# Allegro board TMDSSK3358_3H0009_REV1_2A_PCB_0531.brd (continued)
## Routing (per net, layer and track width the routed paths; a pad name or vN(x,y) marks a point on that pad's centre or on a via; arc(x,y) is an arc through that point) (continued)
GND_IN: length 38
  TOP w0.889: J9.2 110.25,11.48 ; J9.2 108.1,13.63 ; J9.2 105.96,11.48 ; J9.2 108.1,9.33 ; J9.3 114.74,10.07 ; J9.3 114.74,6.39 ; J9.3 111.06,10.07 ; J9.3 111.06,6.39
  BOTTOM w0.889: 111.06,6.39 J9.3 ; J9.3 114.74,10.07 ; J9.3 114.74,6.39 ; J9.3 111.06,10.07 ; J9.2 110.25,11.48 ; J9.2 105.96,11.48 ; J9.2 108.1,9.33 ; J9.2 108.1,13.63
GND_OSC0: length 22.4
  TOP w0.508: v2(64.19,34.09) 64.87,33.4 C95.2
  BOTTOM w0.305: v2(64.19,34.09) 64.45,33.82 65.2,33.82 65.59,34.21 U26.V11
  BOTTOM w0.381: C250.1 60.41,26.44 57.33,26.44 55.82,27.95 55.82,29.19 56.37,29.75 56.37,30.51 57,31.14 60.36,31.14 C245.1 62.22,32.44 62.22,32.75 63.28,33.82 63.92,33.82 v2(64.19,34.09)
GND_OSC1: length 10.3
  BOTTOM w0.381: C249.1 C247.1 89.02,28.82 88.73,28.82 88.27,29.28 87.37,29.28 87.08,28.99 82.52,28.99 82.09,29.41 U26.A5
GNDA_ADC: length 23.3
  TOP w0.381: 84.26,28.79 FB8.1 84.3,28.73 85.39,27.64 88.19,27.64 89.03,26.8 92.68,26.8 93.73,27.84 93.73,30.34 92.95,31.11 92.95,32.98 92.53,33.4 90.04,33.4 89.66,33.02 88,33.02 87.93,33.09 87.46,33.09 87.45,33.08 87.31,33.08 R72.1
  BOTTOM w0.305: v2(77.54,31.41) 77.14,31.81 U26.E8
GNDA_TSC: length 12.8
  TOP w0.508: R72.2 85.9,32.84 83.51,32.84 v2(83.11,33.24) 82.93,33.43 82.93,34.92 82.58,35.28 81.51,35.28 C89.2 C88.2
  LYR4_PWR1 w0.381: v2(83.11,33.24) 81.95,33.24 80.92,32.21 v2(79.14,32.21)
  BOTTOM w0.381: v2(83.11,33.24) 83.11,33.13 82.59,32.61
V1_8D: length 16
  TOP w0.381: C170.1 52.59,6.36 U12.16 ; U11.16 49.16,13.35 49.17,13.34 C149.1 49.07,12.75 v1(48.77,12.45)
  TOP w0.508: R58.2 16.97,37.41 v1(16.97,38.18) ; v1(50.72,7.92) 50.72,7.42 51.79,6.35 C170.1 ; R57.2 15.45,37.67 v1(15.45,37.92)
  BOTTOM w0.254: C276.1 35.97,14.96 U31.36
  BOTTOM w0.381: U29.16 51.67,20.7 51.29,21.08 C264.1
  BOTTOM w0.508: v1(49.66,21.46) 50.09,21.46 50.42,21.13 C264.1 ; C276.1 v1(35.31,16.34)
  BOTTOM w0.635: C270.1 v1(34.36,17.67)
  vias: v1(16.21,38.18) v1(17.86,38.18) v1(18.62,38.18) v1(29.17,15.19) v1(29.17,14.43) v1(30.05,15.19) v1(30.05,14.43)
V3_3AUD:
  vias: v1(35.2,8.33) v1(35.9,7.82) v1(40.42,6.73) v1(40.79,7.8)
V3_3D: length 115.7
  TOP w0.254: J1.4 32.81,34.66 v1(32.59,34.87) ; v1(97.48,18.14) 97.48,18.57 97.33,18.72 97.01,18.72 96.88,18.59 U10.1 ; 45.61,4.71 FB11.1
  TOP w0.305: U10.15 v1(96.39,17.02) ; U12.3 v1(58.7,7.66) ; U10.14 v1(98.21,16.52)
  TOP w0.381: U12.1 59.26,6.36 58.81,5.91 58.81,5.43 C180.1 ; U5.5 v1(40.71,51.83) ; C38.1 94.36,43.85 v1(94.87,44.36) 95.5,43.72 C39.1 ; U11.1 58.41,13.35 C151.1 v1(58.55,12.51) ; U11.2 58.32,14 v1(58.46,14.14)
  TOP w0.508: C15.1 42.29,53.59 42.32,53.56 v1(42.32,53.51) ; v1(44.34,4.71) 45.61,4.71 44.79,3.89 v1(44.79,3.51) ; R13.2 37.78,54.48 v1(37.5,54.76) ; C35.1 55.12,43.64 54.48,44.28 54.48,44.28 v1(54.46,44.3) 54.44,44.3 53.97,43.83 C34.1 ; v1(47.81,24.13) 47.45,24.49 R76.1 ; R82.1 v1(39.58,21.08) ; J2.1 62.51,23.4 62.1,22.99 61.72,22.99 v1(61.47,22.73) ; FB11.1 v1(46.95,4.71) ; C5.1 44.89,60.58 44.83,60.52 v1(44.83,60.2) ; v1(50.43,57.24) C12.1 ; R16.1 v1(51.31,51.56) ; C180.1 v1(59.11,4.41) ; v1(40.52,57.91) 40.95,57.91 41.08,57.78 C11.1 ; v1(89.05,11.61) 88.61,11.16 R90.1 ; C133.1 v1(41.33,25.98) ; v1(42.33,21.08) R83.1 ; C16.1 44.32,53.56 44.32,53.56 v1(44.32,53.51) ; v1(39.75,18.29) 40.45,18.29 40.91,17.83 C139.1 ; U4.5 v1(49.78,51.95) ; C14.1 47.53,56.64 47.43,56.74 v1(47.05,56.74) 46.56,56.74 46.54,56.77 C13.1 ; R86.2 v1(92.58,15.42) ; C184.2 101.17,2.85 v1(101.17,1.95) ; U9.6 v1(46.93,23.29)
  LYR4_PWR1 w0.635: J8.4 34.15,47.24 ; J8.4 32.14,47.24 ; J8.4 33.15,46.24 ; J8.4 33.15,48.25 ; J11.1 102.35,13.21 ; J11.1 100.34,13.21 ; J11.1 101.35,14.21
  LY6_SIG2 w0.381: v1(55.75,21.67) 56.47,21.67 57.22,22.42 61.07,22.42 61.39,22.73 v1(61.47,22.73)
  BOTTOM w0.203: 54.63,43.53 U24.4 ; U23.4 95.01,43.69
  BOTTOM w0.254: U28.42 33.54,29.58 C246.1 ; U31.45 41.08,16.26 v1(41.33,16.51) 41.58,16.26 U31.46 ; U31.44 40.58,16.64 40.64,16.69 C272.1 ; v1(94.87,44.36) 95.01,44.21 95.01,43.69 ; 54.63,43.53 54.63,44.14 v1(54.46,44.3)
  BOTTOM w0.305: U16.20 40.64,57.79 v1(40.52,57.91) ; U28.20 42.92,21.72 43.05,21.58 C265.1 ; U28.28 v1(38.92,24.51) ; U16.27 44.82,60.19 v1(44.83,60.2) ; C272.1 40.26,17.27 40.13,17.4 v1(39.75,17.4) ; U29.3 v1(52.97,23.8) ; U28.31 37.42,21.97 37.59,21.8 C266.1 ; v1(39.94,32.55) 39.98,32.55 40.42,33 U28.56 ; v1(47.05,56.74) 47.14,56.74 47.09,56.79 U16.4 ; U16.14 v1(42.32,53.51) ; U16.10 v1(44.32,53.51) ; U29.2 52.32,24.07 v1(52,23.75) 51.67,24.07 U29.1
  BOTTOM w0.381: v1(98.21,16.52) 97.1,16.52 C275.1 ; C246.1 32.9,29.59 v1(32.47,29.16) ; C265.1 v1(42.33,21.08) ; R110.2 v1(49.74,53.29) ; C194.2 49.54,52.2 v1(49.78,51.95) ; R225.2 62.95,21.33 62.95,21.96 62.18,22.73 v1(61.47,22.73) ; C266.1 v1(36.83,21.08)
  BOTTOM w0.508: FB16.1 v1(104.3,46.15) ; v1(40.85,37.41) 40.15,37.41 FB18.1 ; C259.1 49.23,22.99 v1(48.73,23.48) ; v1(37.5,54.76) 37.78,54.48 R13.2 ; v1(101.17,1.95) J12.5 ; v1(62.45,48.31) 62.45,48.18 62.86,47.76 FB15.1 v1(63.99,47.23) ; C196.2 43.96,52.32 44.21,52.58 v1(44.63,52.58) ; R118.2 v1(42.6,50.55) ; 95.77,16.2 95.77,16.4 v1(96.39,17.02) ; v1(32.59,34.87) 32.65,34.93 32.65,34.93 33.02,35.3 33.1,35.38 C231.1 ; R221.2 v1(47.81,24.13) ; v1(89.05,11.61) 89.15,11.61 89.93,12.39 89.93,13.66 90.86,14.59 90.86,15.2 90.69,15.36 90.69,16.71 91.2,17.22 R234.2 v1(91.52,18.03)
  vias: v1(53.85,29.01) v1(54.29,28.04) v1(114.17,49.28) v1(114.43,48.64) v1(114.55,49.91)
V5_0D: length 24.3
  TOP w0.508: R15.2 32.52,52.2 26.63,46.3 20.15,46.3 19.52,46.93 18.88,46.93
  BOTTOM w0.203: 22.4,47.03 U20.E1 U20.E2 22,46.99
  vias: v1(16.34,47.57) v1(17.23,47.57) v1(18.12,47.57) v1(18.88,47.57)
V5_0D_EN: length 1.7
  BOTTOM w0.14: U20.A4 20.86,49.86 20.15,49.86 R120.1
VBAT: length 38.1
  TOP w0.254: 25.87,40.45 U7.2
  TOP w0.508: C43.1 112.12,43.24 112.24,43.36 v1(112.29,43.36) ; C46.1 116.96,42.33 117.06,42.43 117.75,42.43 v1(117.89,42.57) ; C63.1 110.17,38.77 110.04,38.64 v1(110.04,38.58) ; v1(113.97,43.51) 113.92,43.46 113.92,43.4 113.7,43.18 C42.1
  TOP w0.635: TP11.1 113.08,25.4 ; TP11.1 112.01,26.47 ; TP11.1 110.95,25.4 ; TP11.1 112.01,24.33
  LY5_PWR2 w0.635: TP5.1 119.18,48.51 ; TP5.1 118.11,49.58 ; TP5.1 117.04,48.51 ; TP11.1 112.01,26.47 ; TP11.1 112.01,24.33 ; TP11.1 113.08,25.4
  BOTTOM w0.14: 117.02,41.58 U25.13
  BOTTOM w0.203: v1(112.29,43.36) 112.65,43.01 U25.3 ; 115.25,35.43 115.25,35.08 115.37,34.95 v1(115.72,34.95) ; 115.25,35.43 115.05,35.63 U25.28 ; 115.25,35.43 115.45,35.63 U25.27 ; v1(110.04,38.58) 110.1,38.64 U25.41 ; U25.6 113.85,43.39 v1(113.97,43.51) ; U25.36 111.85,35.87 111.62,35.65 ; U25.47 110.11,41.04 109.85,41.3 ; U25.23 117.83,37.44
  BOTTOM w0.254: U20.A2 U20.A1
  BOTTOM w0.381: 117.02,41.58 117.02,41.7 v1(117.89,42.57) ; v1(111.3,34.95) 111.3,35.33 111.62,35.65 ; 109.85,41.3 109.65,41.5 v1(109.02,41.5) ; 117.83,37.44 118.16,37.44 v1(118.41,37.19)
  BOTTOM w0.508: R112.2 v1(130.18,51.18) ; R113.2 v1(129.03,51.18) ; R111.2 v1(132.21,51.94) ; R114.2 127.89,51.44 v1(128.14,51.18) ; R116.2 v1(125.6,51.18)
  BOTTOM w0.635: TP11.1 113.08,25.4 ; TP11.1 112.01,26.47 ; TP11.1 112.01,24.33 ; TP11.1 110.95,25.4
  vias: v1(22.43,50.5) v1(23.42,50.53) v1(25.23,43.76) v1(25.61,41.73) v1(25.61,41.1) v1(25.86,43.76) v1(30.05,24.71) v1(30.05,23.95) v1(30.82,24.71) v1(30.82,23.95) v1(31.96,14.55) v1(31.96,13.67) v1(32.72,14.55) v1(32.72,13.67) v1(61.84,3.62) v1(62.29,2.67) v1(86.36,4.83) v1(87.12,4.83) v1(87.25,1.78) v1(108.54,50.18) v1(109.09,49.53) v1(109.18,50.18) v1(109.6,24.26) v1(109.6,22.99) v1(109.6,20.19) v1(110.74,24.26) v1(110.74,22.99) v1(110.74,20.19) v1(112.14,23.88) v1(112.14,22.61) v1(112.14,21.34) v1(112.14,20.19) v1(113.28,23.88) v1(113.28,22.61) v1(113.28,21.34) v1(113.28,20.19) v1(113.54,25.15) v1(114.43,20.19) v1(115.7,20.19) v1(117.02,24.13) v1(117.02,22.86) v1(117.02,21.59) v1(117.09,25.53) v1(117.74,33.47) v1(120.27,45.97) v1(120.27,45.21) v1(120.27,44.32) v1(120.27,43.56) v1(120.9,45.98) v1(121.03,45.21) v1(121.03,44.32) v1(121.03,43.56) v1(121.92,44.83)
VBAT_WLAN:
  vias: v1(19.64,39.7) v1(19.73,38.86) v1(20.28,38.3)
VBAT_WLAN_OUT: length 1
  BOTTOM w0.381: U22.2 19.74,44.81 20.31,44.24
VBUS_DET: length 3.5
  BOTTOM w0.254: R103.1 39.6,56.46 40.11,56.46 40.44,56.79 U16.18
  BOTTOM w0.381: R101.2 R103.1
VDD_1V8FT: length 13.3
  BOTTOM w0.305: U28.49 36.92,32.65 v1(36.96,32.6) ; 47.73,27.08 U28.12 ; v1(44.91,31.27) 44.42,31.76 U28.64 ; C251.2 33.66,27.08 U28.37
  BOTTOM w0.508: v1(50.5,26.04) C253.2 49.2,26.04 48.16,27.08 47.73,27.08 ; v1(32.7,32.26) 33.2,32.77 C241.2 ; v1(32.72,27) C251.2
VDD_CORE: length 22.6
  TOP w0.254: v2(72.74,29.81) 72.74,30.14 72.75,30.15 ; v1(90.8,38.98) 90.3,39.48 90.3,39.5 89.77,40.02 C49.1 88.15,40.02 C51.1 87.96,40 87.66,40.3 87.66,40.45 87.64,40.5 87.63,40.51 87.63,40.51 v1(87.63,40.51)
  TOP w0.381: C100.1 70.93,32 v2(71.14,32.21) ; v2(73.54,35.41) 73.59,35.36 C92.1 ; 72.73,31.4 72.73,31.4 v2(72.74,31.41) 73.33,32 C102.1 ; C101.1 72.15,32.21 v2(72.74,32.21) ; C91.1 71.25,34.72 v2(71.14,34.61)
  BOTTOM w0.14: 71.14,36.21 v2(71.14,36.21)
  BOTTOM w0.203: 110.24,39.84 U25.44
  BOTTOM w0.305: U26.L7 72.34,31.01 v2(72.74,31.41) U26.K8 ; U26.L8 72.34,31.82 v2(72.74,32.21) 72.34,32.61 U26.L9 ; v2(75.94,29.81) 75.94,29.81 ; 75.94,29.81 U26.F6 ; 75.94,29.81 75.54,30.21 U26.G6 ; U26.N8 70.74,31.82 v2(71.14,32.21) 70.74,32.61 U26.N9 ; v2(75.14,34.61) U26.H11 ; U26.K6 v2(72.74,29.81) 72.74,29.81 U26.L6 ; U26.G10 v2(75.14,33.01) ; U26.M13 71.14,36.21 U26.N13 ; U26.F7 v2(75.94,30.61) 75.54,31.01 U26.G7 ; U26.N12 v2(71.14,34.61) U26.M11 ; U26.J12 v2(73.54,35.41) 73.14,35.02 U26.K12
  BOTTOM w0.381: 110.24,39.84 109.9,39.84 109.87,39.81 108.98,39.81 108.58,39.42
  vias: v1(103.33,39.14) v1(103.38,40.67) v1(103.35,39.9) v1(104.19,40.64) v1(104.96,41.96) v1(104.98,41.3) v1(104.98,40.64) v1(105.92,40.64) v1(105.98,41.91)
VDD_FTVPHY: length 4.8
  BOTTOM w0.305: U28.4 47.65,31.08
  BOTTOM w0.508: FB19.2 50.36,30.99 C242.1 48.11,30.99 48.02,31.08 47.65,31.08
VDD_FTVPLL: length 5
  BOTTOM w0.305: U28.9 47.35,28.58 47.54,28.77
  BOTTOM w0.508: FB20.2 50.65,28.66 49.19,28.66 C248.1 48.82,29.03 47.8,29.03 47.54,28.77
VDD_MPU_AM335X: length 7
  TOP w0.305: C82.1 76.55,36.83 76.23,36.51 76.23,36.51 v2(75.94,36.21) ; C86.1 77.47,34.54 v2(76.74,33.81) ; v2(74.34,36.21) 74.45,36.32 C85.1
  BOTTOM w0.14: v2(75.94,36.21) 75.94,36.21
  BOTTOM w0.305: v2(75.94,34.61) U26.F12 ; U26.G13 75.94,36.21 U26.F13 ; U26.J13 73.94,35.82 v2(74.34,36.21) U26.H13 ; U26.F11 v2(76.74,33.81) 76.34,33.41 U26.F10
  vias: v1(89.8,30.72) v1(90.19,30.22) v1(90.3,29.6) v1(101.11,29.54) v1(101.11,28.77) v1(101.87,28.52) v1(103.12,29.46) v1(103.12,28.57) v1(103.67,33.24) v1(103.73,31.44) v1(104.39,29.46) v1(104.39,28.57) v1(104.71,32.39) v1(104.71,31.5) v1(104.82,33.18) v1(106.23,33.12)
VDD_RTC: length 2.4
  TOP w0.381: C122.1 79.68,29.29 78.87,29.29 v2(78.34,29.81)
  BOTTOM w0.305: U26.D6 v2(78.34,29.81)
VDDA_ADC: length 2.5
  TOP w0.381: C99.1 79.8,32.13 79.34,31.67 78.6,31.67 v2(78.34,31.41)
  BOTTOM w0.305: v2(78.34,31.41) 78.34,31.42 U26.D8
VDDH_PHY: length 15.1
  TOP w0.508: C41.1 97.72,43.69 v1(97.59,43.81) 97.59,44.91 97.03,45.47 R26.1 94.77,45.47 93.6,44.29 93.6,38.71 94.72,37.59 R55.1
  BOTTOM w0.203: U23.10 97.41,43.63 v1(97.59,43.81)
VDDH_PHY2: length 14.7
  TOP w0.381: R54.1 54.22,37.92 54.22,38.72 54.55,39.05 54.66,39.05 55.05,39.43 55.05,39.96 54.61,40.4 54.17,40.4 52.89,41.68 R47.2
  TOP w0.508: v1(52.89,44.25) R47.2 ; C37.1 57.4,43.31 v1(57.03,43.69)
  LY3_SIG1 w0.508: v1(57.03,43.69) 56.77,43.94 55.63,43.94 55.19,43.51 53.63,43.51 v1(52.89,44.25)
  BOTTOM w0.203: v1(57.03,43.69) U24.10
VDDL_PHY: length 2.2
  BOTTOM w0.203: U23.47 90.7,41.55
VDDL_PHY2: length 1.8
  BOTTOM w0.203: C223.1 50.82,41.55 U24.47
VDDMPU_MON: length 7.7
  BOTTOM w0.381: U26.A2 80.85,26.5 81.27,26.5 82.38,25.4 82.83,25.4 85.62,22.61 R223.1
VDDS_DDR: length 46.2
  TOP w0.254: v2(79.51,7.2) 79.56,7.15 C174.1 ; C168.1 70.35,7.57 v1(69.77,6.99) ; v1(64.27,15.37) 64.26,15.37 64.26,15.39 64.29,15.37 64.29,15.02 64.34,14.96 C144.1 ; C142.1 77.71,16.57 v2(77.5,16.78) ; C143.1 72.07,16.13 v1(71.43,16.76) ; C175.1 70.78,6.84 v1(70.65,6.97) ; C169.1 69.25,7.35 v1(68.89,7) ; v2(69.91,13.6) 70.01,13.69 C148.1 ; v2(73.91,7.19) 73.81,7.09 C173.1 ; U14.2 87.19,3.8 87.01,3.98 ; C172.1 77.46,6.85 v2(77.11,7.2) ; v2(72.31,10.4) 72.32,10.39 C165.1 ; v2(75.51,13.6) 75.77,13.85 C147.1
  TOP w0.305: C167.2 74.74,8.8 v2(75.51,8.8)
  TOP w0.381: 87.01,3.98 86.82,4.17 86.21,4.17 85.83,4.55 85.79,4.59 85.79,5.06 86.11,5.38 v1(86.11,8.15)
  TOP w0.508: v1(62.41,10.79) 62.65,10.56 C158.1 ; R93.2 86.97,9.02 v1(86.11,8.15) ; v1(87.1,15.72) 87.1,16.48 C140.1
  BOTTOM w0.203: 117.68,40.24 U25.16
  BOTTOM w0.254: v2(79.13,14.55) 79.13,14.57 79.09,14.52 79.11,14.5 U32.R1 ; 118.27,40.39 117.83,40.39 117.68,40.24
  BOTTOM w0.305: U32.G7 72.71,9.99 v2(72.31,10.4)
  BOTTOM w0.381: U32.H9 v2(73.91,7.19) ; U32.D2 v2(69.91,13.6) ; v1(71.43,16.76) 71.43,15.04 71.75,14.73 71.75,14.16 U32.F1 ; U32.N1 77.51,16.73 77.56,16.78 v2(77.5,16.78) ; U32.D9 69.77,7.05 v1(69.77,6.99) ; U32.R9 v2(79.51,7.2) ; U32.N9 v2(77.11,7.2) ; v1(64.32,8.89) 64.81,8.39 U32.A8 ; U32.C9 68.89,6.97 v1(68.89,7) ; U32.K8 v2(75.51,8.8) ; v1(68.77,15.59) 69.51,14.85 U32.C1 ; v1(70.65,6.97) 70.65,7.13 U32.E9 ; U32.K2 v2(75.51,13.6) ; U32.A1 v2(68.31,13.6) U32.B2 ; U32.H2 v2(73.11,13.6)
  BOTTOM w0.508: v1(87.1,15.72) 86.82,15.44 R237.1 ; C140.1 86.69,17.77 v1(86.95,18.03)
  vias: v1(59.81,11.91) v1(60.82,12.21) v1(61.31,14.61) v1(61.31,13.97) v1(61.33,13.34) v1(120.14,34.29) v1(120.9,35.05) v1(120.9,34.29) v1(121.79,35.05) v1(121.79,34.29) v1(122.68,36.58) v1(122.68,35.81) v1(122.68,35.05) v1(122.68,34.29) v1(123.44,35.81) v1(123.44,35.05) v1(123.44,34.29)
VDDS_DDR3_AM335X: length 4
  BOTTOM w0.305: v2(75.94,29.01) U26.G5 ; U26.L5 72.74,29.01 v2(72.74,29.01) U26.K5 ; U26.H5 v2(74.34,29.01) 74.34,29.01 U26.J5 ; U26.E5 v2(76.74,29.01) 76.74,29.01 U26.F5
  vias: v1(59.33,17.49) v1(59.63,18.64) v1(60.01,18.13) v1(60.44,18.6) v1(61.72,20.7)
VDDSHV1: length 73.1
  TOP w0.508: 64.77,49.53 66.92,49.53 68.17,50.77 71.08,50.77 71.44,50.41 74.05,50.41 76.24,52.6 89.4,52.6 89.62,52.38 91.19,52.38 93.01,50.56 96.44,50.56 v1(96.79,50.21) 96.79,49.42 v1(96.86,49.35)
  LY6_SIG2 w0.508: v1(96.79,50.21) 96.79,49.42 v1(96.86,49.35) 96.98,49.23 103.83,49.23 109.85,55.25 109.85,55.25 110.01,55.4 112.81,55.4 113.68,54.53 120.21,54.53 120.26,54.48 123.2,54.48 126.24,51.44 v1(126.24,51.18)
  BOTTOM w0.254: U26.P8 v2(69.54,31.41) U26.P7
  BOTTOM w0.508: v1(126.24,51.18) 126.75,51.69 R115.1 ; v1(96.86,49.35) 96.45,48.95 R123.1
VDDSHV2: length 2
  TOP w0.305: v2(69.54,33.81) 69.78,33.57 C96.1
  BOTTOM w0.305: U26.P10 v2(69.54,33.81) ; U26.P11 69.94,34.22 v2(69.54,34.61)
  vias: v1(64.53,43.76) v1(64.78,43.12)
VDDSHV3: length 119.6
  TOP w0.508: SW3.1 SW3.2 127.15,34.14 v1(127,34.29) ; R22.2 51.37,49.45 51.76,49.85 52.53,49.85 52.54,49.85 v1(52.57,49.85)
  LY3_SIG1 w0.381: v1(52.57,49.85) 52.06,50.37 52.06,51.94 52.72,52.6 55.76,52.6 56.15,52.99 57.53,52.99 58.16,52.35 67.43,52.35 69.21,50.57 69.21,49.13 v1(70.33,48) 70.33,47.45 v1(70.41,47.37)
  LY3_SIG1 w0.508: v1(127,34.29) 127,48.02 121.6,53.42 120.28,53.42 116.18,57.52 110.6,57.52 108.4,55.32 101.79,55.32 99.07,58.04 98.54,58.04 97.64,57.14 95.59,57.14 93.55,55.1 91.36,55.1 90.47,56 78.78,56 77.3,54.52 v1(75.95,54.52) v1(74.81,54.52)
  LY6_SIG2 w0.508: v1(75.95,54.52) 75.61,54.86 75.15,54.86 v1(74.81,54.52) 74.81,53.49 73.73,52.41 73.73,50.86 73.35,50.49 72.81,50.49 v1(70.33,48) 70.33,47.45 v1(70.41,47.37)
  BOTTOM w0.305: v2(69.54,35.41) U26.P12 ; U26.P13 v2(69.54,36.21)
VDDSHV4: length 43.9
  TOP w0.254: v1(103.13,65.96) 103.44,65.66 U1.10
  TOP w0.305: v2(74.34,37.01) 74.04,37.01 73.97,37.08 C80.1
  TOP w0.508: v1(99.35,63.75) C3.1 99.18,62.56 96.95,62.56 v1(96.93,62.59) ; R1.2 v1(101.15,68.76) ; v1(96.58,68.33) C1.1 ; R4.2 v1(101.98,65.84) ; R5.2 v1(99.3,64.82) ; R2.2 v1(108.08,67.18) ; R3.2 v1(101.91,66.93)
  BOTTOM w0.305: U26.J14 v2(74.34,37.01) U26.H14 v2(75.14,37.01) ; v1(96.58,68.33) 97.54,68.33 J4.4
  BOTTOM w0.508: v1(96.93,62.59) 96.9,62.56 v1(96.27,62.56) 94.36,60.66 94.36,56.13 93.09,54.86 91.95,54.86 90.69,56.12 80.19,56.12 77.56,53.49 77.56,50.18 v1(77.56,50.18) 77.56,50.07 78.05,49.58 v1(78.05,49.58)
VDDSHV5: length 2
  TOP w0.305: C79.1 72.32,37.08 72.39,37.01 v2(72.74,37.01)
  BOTTOM w0.254: U26.L14 72.34,36.62 v2(72.74,37.01) U26.K14
VDDSHV6: length 70.9
  TOP w0.254: 98.81,59.3 U2.1
  TOP w0.381: C116.1 70.28,29.01 v2(69.54,29.01) v2(69.54,29.81) ; v1(103.36,30.84) 103.73,30.46 R74.2 ; v1(85.72,44.3) 85.72,44.31 86.93,44.31 87.26,44.64 U6.5 ; U8.8 102.23,28 102.46,28.23 C115.1 102.19,29.08 101.85,29.42 v1(101.85,29.43)
  TOP w0.508: C126.1 C127.1 62.51,26.57 v2(63.22,26.57) ; 98.81,59.3 R11.2 97.59,59.31 97.03,58.75 97.03,58.42 v1(96.65,58.04) ; v1(88.77,33.66) 89.15,34.04 C93.1
  LY3_SIG1 w0.508: v1(96.65,58.04) 96.72,58.04 97.63,58.95 100.14,58.95 102.29,56.79 106.96,56.79 111.32,61.16 113.81,61.16 118.99,55.97 120.68,55.97 v1(123.7,52.96)
  BOTTOM w0.14: 77.54,33.81 v2(77.54,33.81)
  BOTTOM w0.254: U26.F14 76.34,36.62 v2(75.94,37.01) U26.G14
  BOTTOM w0.305: U26.P6 v2(69.54,29.81) ; v2(69.54,29.01) U26.P5 ; U26.E13 v2(77.54,36.21)
  BOTTOM w0.381: U26.E12 77.14,35.01 v2(76.74,34.61) ; R191.2 87.46,33.66 v1(88.77,33.66) ; v1(85.72,44.3) 85.72,44.3 85.72,44.32 85.72,44.32 C206.1 ; U26.E10 77.14,33.41 77.54,33.81 ; R131.2 77.27,46.88 v1(76.71,47.45) ; C258.1 C255.1 60.35,25.15 60.53,24.96 60.53,24.65 v1(60.59,24.58) ; v2(77.54,33.81) 77.14,34.21 U26.E11 ; v1(83.06,43.05) 83.06,43.94 82.99,44.01 R142.2 ; R141.2 84,44.01 84.07,43.94 v1(84.07,43.05) ; U26.N5 U26.P5 ; v1(87.77,38.82) 87.77,38.82 87.77,38.83 87.8,38.83 87.77,38.8 87.76,38.8 87.44,38.48 R177.2
  BOTTOM w0.508: R219.1 99.23,28.11 v1(99.23,28.95) ; R179.2 R177.2 ; R102.2 v1(13.29,57.61) ; R117.2 v1(123.7,52.96)
  vias: v1(34.67,44.45) v1(36.7,44.45) v1(38.73,44.45) v1(40.77,44.45) v1(42.8,44.45) v1(44.83,44.45) v1(46.86,44.45) v1(81.34,43.05) v1(82.17,43.05)
ACC_INT1: length 51.8
  TOP w0.102: v2(79.14,36.21) 78.76,35.83 78.18,35.83 77.94,36.08 77.94,37.06
  TOP w0.14: 77.94,37.06 77.94,37.18 78.17,37.41 79.31,37.41 79.81,37.92 79.81,39.42 81.2,40.81 83.22,40.81 86.03,38 88.28,38 88.65,37.64 88.65,36.58 88.91,36.31 90.79,36.31 91.4,36.92 92.35,36.92 92.57,36.7 93.37,35.9 93.37,35.06 95.06,33.37 95.36,33.37 95.7,33.03 95.7,32.7 97.42,30.98 98.28,30.98 99.73,29.52 99.73,28.14 100.6,27.28 100.6,22.81 100.6,22.5 100.6,21.64 100.6,18.81 99,17.21 99,16.41 97.86,15.27 96.2,15.27 95.91,15.57 95.91,15.74 U10.11
  BOTTOM w0.14: U26.C13 v2(79.14,36.21)
ACC_INT2: length 65.1
  TOP w0.14: v1(96,14.75) 97.86,14.75 99.37,16.26 99.37,16.95 100.97,18.54 100.97,21.49 100.97,21.49 100.97,22.66 100.97,22.96 100.97,22.96 100.97,27.43 100.11,28.28 100.11,29.66 98.43,31.35 97.61,31.35 96.67,32.3 96.67,33.08 94.65,35.1 94.12,35.1 93.74,35.47 93.74,36.05 92.68,37.11 92.5,37.29 90.78,37.29 90.07,38 88.98,38 88.61,38.37 86.24,38.37 83.56,41.05 80.18,41.05 79.14,40.02 v2(79.14,39.41)
  LY3_SIG1 w0.127: v1(96,14.75) 96.36,14.75 97.28,13.83 97.28,11.6 93.53,7.84 v1(89.52,7.84)
  BOTTOM w0.14: R243.1 R244.2 88.02,6.35 89.52,7.84 v1(89.52,7.84) ; U26.C18 v2(79.14,39.41)
AM335X_AUDA_BCLK: length 84.1
  LY3_SIG1 w0.127: v1(36.8,18.75) 36.39,19.16 36.39,21.27 38.17,23.05 39.59,23.05 40.86,24.33 40.86,24.81 39.87,25.8 39.87,26.91 37.41,29.38 37.41,30.35 35.86,31.89 35.86,33.9 35.86,34.39 31.68,38.57 31.68,39.21 31.64,39.25 31.64,39.26 31.13,39.77 31.13,41.69 30.62,42.2 30.62,44.03 32.03,45.44 36.04,45.44 36.33,45.73 48.69,45.73 49.77,44.65 52.38,44.65 53.23,45.5 56.79,45.5 57.3,45 59.22,45 59.42,44.79 62.01,44.79 66.53,40.27 66.72,40.27 66.91,40.27 66.91,40.27 70.25,40.27 70.67,39.86 73.34,39.86 73.78,39.41 v2(74.34,39.41)
  BOTTOM w0.14: v2(74.34,39.41) 74.74,39.01 U26.H17 ; U31.38 37.58,16.49 37.33,16.74 37.33,17.51 36.8,18.04 v1(36.8,18.75)
AM335X_AUDA_DIN: length 89.6
  LY3_SIG1 w0.127: v1(37.47,18.16) 36.67,18.16 35.88,18.95 35.88,21.48 37.96,23.56 38.83,23.56 39.36,24.1 39.36,24.74 39.18,24.92 39.18,25.62 39.36,25.81 39.36,26.69 36.75,29.31 36.75,30.28 35.35,31.68 35.35,34.11 31.13,38.33 31.13,39.04 30.62,39.56 30.62,41.42 30.11,41.93 30.11,44.24 31.82,45.95 35.83,45.95 36.99,47.11 36.99,47.44 37.81,48.26 41.92,48.26 43.6,46.58 48.56,46.58 49.98,45.16 52.13,45.16 53.14,46.16 53.87,46.16 54.43,46.72 54.79,46.72 55.51,46.01 57.28,46.01 57.78,45.5 59.43,45.5 59.63,45.3 62.23,45.3 64.26,43.28 64.26,43.06 66.81,40.5 70.43,40.5 70.79,40.14 73.85,40.14 74.17,39.81 74.5,39.81 75.14,39.17 v2(75.14,38.61)
  BOTTOM w0.14: U31.40 38.58,17.51 37.93,18.16 v1(37.47,18.16) ; U26.H16 74.74,38.21 v2(75.14,38.61)
AM335X_AUDA_DOUT: length 57.5
  TOP w0.14: v1(47.88,17.27) 47.37,17.78 45.35,17.78 43.62,16.06 39.69,16.06 38.97,16.78 v1(38.97,17.96)
  LY6_SIG2 w0.127: v2(74.43,40.39) 73.14,39.1 73.14,38.45 73.39,38.21 73.7,38.21 73.93,37.98 73.93,35.25 72.9,34.22 72.37,34.22 69.96,31.81 69.35,31.81 69.13,31.58 69.13,31.25 68.9,31.02 68.59,31.02 68.35,30.78 68.35,29.98 68.34,29.98 68.34,27.99 68.16,27.81 67.68,27.81 67.06,27.19 67.06,25.67 63.41,22.02 63.07,22.02 62.17,21.12 62.17,20.52 61.91,20.26 60.14,20.26 58.79,18.91 58.09,18.91 57.22,18.03 56.13,18.03 55.12,17.02 53.56,17.02 53.55,17.03 53.13,17.03 52.86,16.76 50.55,16.76 50.04,17.27 v1(47.88,17.27)
  BOTTOM w0.14: U26.H18 74.74,40.08 v2(74.43,40.39) ; U31.41 39.08,17.26 38.97,17.37 v1(38.97,17.96)
AM335X_AUDA_FSX: length 80.7
  LY3_SIG1 w0.127: v1(37.85,17.22) 37.97,17.34 37.97,18.58 37.61,18.94 37.61,21.18 38.97,22.54 40.83,22.54 41.9,23.62 41.9,24.78 40.89,25.8 40.89,26.7 38.32,29.26 38.32,30.56 37.41,31.47 37.41,34.25 33.79,37.86 33.11,37.86 32.19,38.78 32.19,39.42 32.15,39.46 32.15,39.47 31.64,39.98 31.64,42.43 32.71,43.5 37.1,43.5 37.61,44.01 48.51,44.01 50.47,42.05 58.81,42.05 59.08,42.33 61.86,42.33 62.44,41.74 63.78,41.74 65.94,39.59 66.24,39.59 66.24,39.59 67.19,39.59 67.19,39.59 69.62,39.59 70.09,39.11 72,39.11 72.34,38.77 72.34,38.45 72.58,38.22 73.05,38.22 73.28,37.99 73.36,37.99 v2(73.54,37.81)
  BOTTOM w0.14: v1(37.85,17.22) 37.85,16.89 38.08,16.66 U31.39 ; U26.J15 v2(73.54,37.81)
AM335X_COM_WL_IRQ: length 58
  TOP w0.14: v1(60.91,23.88) 58.62,23.88 58.29,23.55 57.9,23.55 57.83,23.5 57.83,23.5 56.37,23.5 55.77,24.1 55.77,24.47 55.93,24.62 55.93,28.75 55.99,28.82 55.99,29.36 56.92,30.3 60.93,30.3 62.99,32.35 62.99,35.71 61.92,36.77 61.92,38.77 62.19,39.04 62.19,41.74 v2(62.61,42.16) ; U12.4 v1(61.21,8.31)
  BOTTOM w0.14: v2(62.61,42.16) 63.06,41.72 63.06,40.39 64.02,39.42 67.13,39.42 U26.U17 ; v1(61.21,8.31) 61.21,10.53 63.89,13.21 63.89,14.04 65.15,15.3 65.15,21.01 65.04,21.13 63.99,22.18 63.99,22.58 63.39,23.19 61.61,23.19 v1(60.91,23.88)
AM335X_EXT_WAKEUP: length 74.5
  LY3_SIG1 w0.127: v1(48.49,34.75) 48.49,33.19 48.94,32.75 48.94,32.09 51.57,29.45 51.58,29.45 52.52,28.51 60.98,28.51 61.55,29.08 63.23,29.08 63.25,29.07 64.36,29.07 64.5,29.22 65.4,29.22 65.42,29.2 65.74,29.2 66.17,29.63 66.17,31 67.78,32.61 76.34,32.61 v2(76.74,33.01)
  LY6_SIG2 w0.127: v1(89.04,30.93) 88.85,31.12 88.85,31.37 88.15,32.07 87.52,32.07 87.24,32.35 87.24,33.12 85.96,34.4 85.96,34.84 85.3,35.5 84.96,35.5 83.88,36.58 83.88,38.45 82.96,39.37 v1(82.96,41.91) 82.34,41.91 80.22,39.8 79.76,39.8 79.75,39.81 78.18,39.81 77.15,38.78 77.15,37.92 76.64,37.41 75.91,37.41 75.91,37.41 75.78,37.41 75.54,37.17 75.54,34.4 76.33,33.61 76.33,33.42 v2(76.74,33.01)
  BOTTOM w0.14: R173.2 88.83,39.63 88.27,40.19 88.27,40.77 88.02,41.01 86.51,41.01 85.86,41.66 84.87,41.66 84.62,41.91 v1(82.96,41.91) ; v1(89.04,30.93) 89.04,30.87 R211.2 ; R189.2 49.66,34.75 v1(48.49,34.75)
AM335X_EXTINT: length 128.9
  TOP w0.14: C32.1 R29.1 123.84,44.78 v1(124.6,44.01) ; R21.2 49.87,49.89 49.87,50.32 v1(49.33,50.85)
  LY3_SIG1 w0.127: v1(49.33,50.85) 49.33,52.13 51.97,54.77 66.1,54.77 66.78,54.09 66.78,54.08 68.17,52.69 77.75,52.69 77.87,52.81 87.33,52.81 88.07,52.07 88.07,50.95 88.6,50.42 92.73,50.42 v1(93.69,51.39)
  LY6_SIG2 w0.127: v1(124.6,44.01) 124.62,44.03 124.62,50.13 121.6,53.15 113.36,53.15 112.69,53.82 109.35,53.82 108.1,52.57 108.1,51.75 104.29,47.94 97.46,47.94 94.01,51.39 v1(93.69,51.39)
  BOTTOM w0.14: R124.2 95.43,50.22 94.26,51.39 v1(93.69,51.39) 92.67,51.39 90.81,49.53 88.42,49.53 87.45,48.55 87.45,47.49 86.44,46.48 86.44,44.29 84.49,42.33 83.15,42.33 83.14,42.34 82.18,42.34 81.2,41.35 79.51,41.35 79.28,41.12 79.28,40.07 U26.B18 ; v1(124.6,44.01) 127.39,44.01 128.16,43.25 128.16,42.26 128.79,41.63 R167.1
AM335X_GPIO_LED1: length 87
  TOP w0.14: v1(114.3,61.98) 113.94,61.62 106.95,61.62 104.27,58.94 104.27,54.95 105.3,53.92 105.3,50.62 104.21,49.54 99.52,49.54 96.66,52.4 92.99,52.4 90.25,55.14 79.43,55.14 77.99,53.7 72.66,53.7 72.24,54.13 v1(71.7,54.13)
  LY6_SIG2 w0.127: v1(71.7,54.13) 71.7,53.81 71.54,53.65 71.54,53.49 70.45,52.4 70.01,52.4 68.73,51.12 68.73,50.85 66.54,48.66 66.54,47.64 65.24,46.33 65.24,41.77 65.48,41.53 65.48,39.57 65.78,39.27 65.78,38.66 65.41,38.29 65.41,36.54 66.94,35.01 68.1,35.01 68.33,34.78 68.33,33.65 67.94,33.26 v2(67.94,32.21)
  BOTTOM w0.14: v1(114.3,61.98) R100.2 114.31,61.2 Q3.G ; v2(67.94,32.21) U26.T9
AM335X_GPIO_LED2: length 86.1
  LY3_SIG1 w0.127: v1(71.99,53.47) 77.52,53.47 79.15,55.1 88.21,55.1 88.93,54.38 88.93,53.9 89.87,52.96 92.69,52.96 95.96,56.24 96.94,56.24 99.86,53.31 105.52,53.31 v1(106.02,52.81)
  LY6_SIG2 w0.127: v1(114.3,65.79) 112.65,64.14 112.65,59.46 106.02,52.83 v1(106.02,52.81) ; v2(68.74,32.21) 68.34,32.61 68.34,33.18 68.59,33.42 68.9,33.42 69.13,33.65 69.13,35.58 68.89,35.82 66.77,35.82 65.74,36.85 65.74,37.98 65.97,38.21 66.49,38.21 66.73,38.45 66.73,38.99 65.9,39.83 65.9,41.84 65.61,42.13 65.61,46.19 66.87,47.45 66.87,48.52 70.42,52.07 70.59,52.07 v1(71.99,53.47)
  BOTTOM w0.14: Q2.G 114.31,65.01 R98.2 v1(114.3,65.79) ; U26.R9 v2(68.74,32.21)
AM335X_GPIO_LED3: length 81.9
  LY3_SIG1 w0.127: v1(114.55,56.88) 111.72,54.05 100.65,54.05 98.13,56.57 95.82,56.57 93.79,54.53 91.07,54.53 90.17,55.43 79.01,55.43 77.54,53.95 72.82,53.95 71.57,55.21 71.2,55.21 70.94,54.95 70.94,54.27 v1(70.74,54.08)
  LY6_SIG2 w0.127: v2(64.13,31.41) 64.15,31.42 64.15,33.57 63.79,33.92 63.79,34.25 64.29,34.75 64.29,36.66 64.14,36.8 64.14,38.48 63.79,38.84 63.79,39.94 64.23,40.39 64.23,41.13 63.73,41.63 63.73,45.98 65.12,47.37 65.12,48.45 66.49,49.82 66.77,49.82 68.07,51.12 68.07,51.82 69.32,53.06 70.18,53.06 70.74,53.62 v1(70.74,54.08)
  BOTTOM w0.14: 115.46,56.88 v1(114.55,56.88) ; 115.46,56.88 R105.2 ; 115.46,56.88 Q5.G ; v2(64.13,31.41) 64.37,31.65 64.37,31.98 64.67,32.28 65.16,32.28 65.63,31.81 U26.V8
AM335X_GPIO_LED4: length 99.6
  TOP w0.14: v1(119.76,56.9) 117.09,56.9 115.7,58.29 115.7,61.72 114.99,62.43 106.82,62.43 103.52,59.13 103.52,54.43 104.66,53.29 104.66,50.84 104.36,50.53 100.17,50.53 97.3,53.41 92.5,53.41 90.4,55.51 79.14,55.51 77.7,54.07 72.82,54.07 72.12,54.76 v1(71.38,54.76)
  LY6_SIG2 w0.127: v2(64.98,31.88) 64.98,33.53 65.73,34.28 65.73,35.2 64.75,36.17 64.75,39.57 65.17,39.99 65.17,40.98 64.08,42.06 64.08,45.78 65.5,47.19 65.5,48.36 66.63,49.49 66.9,49.49 68.4,50.99 68.4,51.41 69.72,52.73 70.32,52.73 71.21,53.63 71.21,54.27 71.38,54.43 v1(71.38,54.76)
  BOTTOM w0.14: v1(119.76,56.9) R104.2 120.54,56.88 Q4.G ; v2(64.98,31.88) 65.39,31.46 67.19,31.46 U26.U8
AM335X_I2C0_SCL: length 212.4
  TOP w0.14: J2.3 64.51,24.89 65.09,25.47 67.7,25.47 67.98,25.19 67.98,22.44 66.6,21.05 62.5,21.05 62.24,20.79 62.24,20.04 61.52,19.33 61.15,19.33 61,19.48 57.49,19.48 57.15,19.82 56.96,19.82 56.83,19.95 54.81,19.95 53.46,21.31 53.46,24.3 54.78,25.63 54.78,29.17 54.88,29.28 54.88,29.75 54.78,29.86 54.78,31.2 54.29,31.69 54.29,32.13 53.66,32.76 53.45,32.97 53.45,36.34 50.35,39.45 50.35,43.58 48.14,45.79 37.14,45.79 J8.3 ; v1(117.73,46.86) v1(115.44,46.86) ; U10.4 95.39,18.84 95.47,18.92 v1(95.5,18.92) ; U8.6 104.77,25.97 104.31,25.5 v1(104.18,25.5) ; v1(80.28,41.98) 78.69,40.39 78.69,39.17 79.14,38.72 v2(79.14,38.61)
  LY3_SIG1 w0.127: v1(104.18,25.5) 104.85,24.83 108.8,24.83 112.03,28.05 112.03,33.97 118.76,40.7 118.76,45.83 v1(117.73,46.86) ; v1(98.3,29.46) 97.33,28.5 95.11,28.5 91.44,32.17 90.66,32.17 90.47,32.36 90.46,32.36 89.22,33.6 89.22,33.84 88.6,34.46 87.55,34.46 86.91,35.1 86.91,35.35 86.34,35.92 86.34,36.77 84.77,38.33 84.77,38.79 84.51,39.05 83.03,39.05 82.91,38.93 79.45,38.93 v2(79.14,38.61) 78.75,39.01 77.38,39.01 77.13,38.76 77.13,38.45 76.9,38.22 76.58,38.22 76.35,38.45 76.35,39.02 74.59,40.78 73.65,40.78 73.25,40.37 70.99,40.37 70.63,40.73 67.22,40.73 65.25,42.7 65.25,43.67 62.73,46.19 59.05,46.19 58.72,46.52 55.72,46.52 55,47.23 54.22,47.23 53.83,46.85 53.1,46.85 52.37,46.11 51.92,45.67 50.19,45.67 47.93,47.93 45.3,47.93 44.47,48.77 37.22,48.77 35.69,47.24 J8.3
  LY6_SIG2 w0.127: v1(98.3,29.46) 98.3,26.61 99.41,25.5 v1(104.18,25.5)
  BOTTOM w0.14: R142.1 81.86,44.85 81.86,44.51 80.28,42.92 v1(80.28,41.98) ; v1(104.18,25.5) 103.23,24.55 100.95,24.55 99.96,23.57 99.96,21.48 97.33,18.85 95.57,18.85 95.52,18.91 ; v2(79.14,38.61) 78.74,38.21 U26.C16 ; 95.52,18.91 v1(95.5,18.92) ; 95.52,18.91 R232.2 ; R139.2 v1(115.44,46.86) ; R137.2 v1(117.73,46.86)
AM335X_I2C0_SDA: length 228.4
  TOP w0.14: v1(64.41,22.35) 64.44,22.33 65.18,22.33 65.51,22.66 J2.4 ; v1(105.28,25.27) 105.79,25.27 106.05,25.53 U8.5 ; v1(96.77,19.3) 96.62,19.46 94.96,19.46 94.93,19.49 94.56,19.49 94.11,19.04 94.11,18.05 U10.6
  LY3_SIG1 w0.127: v1(114.3,46.86) 114.41,46.75 114.41,41.65 110.49,37.73 110.49,37.03 108.92,35.46 108.92,34.27 109.58,33.61 109.58,26.07 108.78,25.27 v1(105.28,25.27)
  LY6_SIG2 w0.127: v1(105.28,25.27) 104.59,24.58 98.62,24.58 93.8,29.4 92.77,29.4 92.39,29.78 92.39,30.42 91.35,31.46 91.35,31.46 89.98,32.83 89.98,35.02 88.03,36.98 85.19,36.98 85.14,36.92 84.79,36.92 84.54,37.16 84.54,37.51 84.77,37.74 84.77,38.79 83.55,40.01 83.55,43.15 81.39,45.31 v1(80.47,45.31)
  BOTTOM w0.14: R138.2 116.59,46.92 116.16,47.35 114.78,47.35 v1(114.3,46.86) R140.2 ; J8.2 40.41,49.42 44.25,49.42 45.04,50.21 48.56,50.21 48.65,50.31 54.39,50.31 56.6,52.52 56.6,54.22 57.97,55.59 74.77,55.59 75.38,54.99 75.38,54.07 76.27,53.18 76.27,49.8 77.59,48.48 78.56,48.48 79.37,49.29 80.89,49.29 81.19,48.98 81.19,46.68 80.47,45.96 v1(80.47,45.31) ; v1(80.47,45.31) 80.47,44.03 78.74,42.3 78.74,40.71 78.37,40.34 78.37,39.39 U26.C17 ; v1(80.47,45.31) 81.12,45.31 82.41,46.61 83.37,46.61 R141.1 ; v1(105.28,25.27) 104.37,26.19 103.77,26.19 102.51,24.92 100.8,24.92 99.58,23.71 99.58,21.62 97.26,19.3 v1(96.77,19.3) 95.85,19.3 95.66,19.49 94.49,19.49 93.49,18.49 R233.2 92.47,18.49 91.98,18.98 91.13,18.98 90.65,18.5 90.28,18.5 89.79,18 89.79,17.15 89.75,17.1 89.75,15.91 87.62,13.79 87.62,12.78 88.1,12.31 88.1,8.34 86.69,6.93 86.69,6.17 85.54,5.02 66.41,5.02 65.72,4.34 64.15,4.34 62.37,6.12 62.37,8.56 64.53,10.72 64.53,13.99 66.37,15.84 66.37,20.39 v1(64.41,22.35)
AM335X_LCD_AC_BIAS_EN: length 39.6
  TOP w0.14: RP4.4 48.76,38.78 48.56,38.98 48.56,39.68 48.76,39.89 v1(48.76,40.51)
  LY3_SIG1 w0.127: v2(68.74,29.81) 68.34,30.21 67.78,30.21 66.31,28.74 65.23,28.74 65.21,28.76 64.69,28.76 64.41,28.47 62.42,28.47 61.45,27.5 56.36,27.5 56.08,27.22 53.14,27.22 53.14,27.22 52.73,27.22 51.26,28.69 51.26,28.69 50.93,29.02 49.44,29.02 46.74,31.72 46.74,37.69 45.91,38.53 45.91,39.36 46.22,39.67 47.93,39.67 v1(48.76,40.51)
  BOTTOM w0.14: U26.R6 v2(68.74,29.81)
AM335X_LCD_DATA0: length 56.4
  TOP w0.14: R31.2 v1(32.64,41.91) 32.64,41.27 34.29,39.62 RP1.5
  LY6_SIG2 w0.127: v1(32.64,41.91) 35.07,39.48 35.07,35.56 35.34,35.28 35.34,31.87 40.73,26.48 50.69,26.48 51.27,25.9 57.44,25.9 57.64,26.1 61.18,26.1 62.33,24.95 62.33,24.51 v2(61.85,24.03)
  BOTTOM w0.14: v2(61.85,24.03) 61.91,24.09 67.02,24.09 U26.R1 ; R31.2 v1(32.64,41.91)
AM335X_LCD_DATA1: length 54
  TOP w0.14: RP1.4 34.79,40.01 33.66,41.15 v1(33.66,41.91) R32.2
  LY6_SIG2 w0.127: v2(62.59,25.83) 62.56,25.86 62.3,25.86 61.67,26.48 57.49,26.48 57.36,26.35 51.57,26.35 51.01,26.91 40.84,26.91 35.73,32.03 35.73,33.37 35.95,33.6 35.95,39.61 v1(33.66,41.91)
  BOTTOM w0.14: v2(62.59,25.83) 62.69,25.93 63.3,25.93 64.11,25.12 67.01,25.12 67.99,26.1 67.99,26.36 68.3,26.66 68.79,26.66 U26.R2 ; R32.2 v1(33.66,41.91)
AM335X_LCD_DATA2: length 55.8
  TOP w0.14: RP1.3 35.29,40.28 34.67,40.9 v1(34.67,41.55) R33.2
  LY3_SIG1 w0.127: v2(68.74,27.41) 64.45,23.12 64.26,23.12 63.3,22.17 63.09,22.17 62.47,21.55 57.04,21.55 55.41,23.18 53.93,23.18 53.69,22.93 53.67,22.93 53.66,22.92 51.32,22.92 51.21,23.04 48.27,23.04 46.9,24.41 46.9,24.59 44.67,26.82 42.02,26.82 39.66,29.19 39.66,31.97 39.3,32.32 39.3,36.07 34.67,40.7 v1(34.67,41.55)
  BOTTOM w0.14: R33.2 v1(34.67,41.55) ; U26.R3 v2(68.74,27.41)
AM335X_LCD_DATA3: length 59.6
  TOP w0.14: R34.2 v1(35.69,41.91) 35.79,41.8 RP1.2
  LY3_SIG1 w0.127: v2(68.74,28.21) 69.13,27.82 69.13,27.25 64.78,22.89 64.35,22.89 62.63,21.17 56.88,21.17 55.25,22.8 54.09,22.8 53.71,22.42 52.08,22.42 51.96,22.54 48.23,22.54 47.96,22.81 46.78,22.81 46.14,23.45 46.14,23.91 43.61,26.44 41.86,26.44 39.27,29.03 39.27,31.81 38.92,32.16 38.92,35.69 34.23,40.38 34.23,41.74 34.49,42 35.6,42 v1(35.69,41.91)
  BOTTOM w0.14: R34.2 v1(35.69,41.91) ; U26.R4 v2(68.74,28.21)
AM335X_LCD_DATA4: length 50.8
  TOP w0.14: RP1.1 36.37,39.96 36.7,40.28 v1(36.7,41.91) R35.2
  LY6_SIG2 w0.127: v2(63.14,25.5) 63.14,25.87 62.76,26.25 62.44,26.25 61.83,26.86 57.33,26.86 57.2,26.73 51.95,26.73 50.88,27.8 48.89,27.8 48.72,27.63 46.03,27.63 45.21,28.46 40.59,28.46 37.41,31.64 37.41,34.6 36.7,35.31 v1(36.7,41.91)
  BOTTOM w0.14: R35.2 v1(36.7,41.91) ; U26.T1 68.34,26.11 66.96,24.73 63.92,24.73 v2(63.14,25.5)
AM335X_LCD_DATA5: length 49.4
  TOP w0.14: RP2.6 38.49,39.8 37.72,40.57 v1(37.72,41.91) R36.2
  LY6_SIG2 w0.127: v1(37.72,41.91) 37.72,40.49 38.39,39.82 38.39,31.2 40.72,28.87 47.9,28.87 48.32,28.45 50.91,28.45 51.92,27.43 62.4,27.43 62.86,26.96 63.38,26.96 63.61,26.73 63.61,26.23 v2(63.89,25.96)
  BOTTOM w0.14: U26.T2 68.34,27.01 68.03,27.01 67.61,26.59 65.48,26.59 64.9,26 63.93,26 63.93,25.96 v2(63.89,25.96) ; R36.2 v1(37.72,41.91)
AM335X_LCD_DATA6: length 53.5
  TOP w0.14: R37.2 38.33,42.27 38.33,41.29 v1(38.73,40.89) 38.73,40.34 38.99,40.08 RP2.5
  LY3_SIG1 w0.127: v2(67.94,27.41) 66.89,26.37 66.89,26.03 64.35,23.49 64.16,23.49 63.36,23.49 61.8,21.93 57.25,21.93 55.63,23.56 53.76,23.56 53.51,23.3 51.52,23.3 51.27,23.56 49.84,23.56 49.84,23.56 49.47,23.56 49.31,23.56 48.29,24.57 47.46,24.57 44.83,27.2 42.18,27.2 40.1,29.28 40.1,30.29 40.38,30.56 40.38,35.91 39.18,37.11 39.18,40.45 v1(38.73,40.89)
  BOTTOM w0.14: v1(38.73,40.89) 38.33,41.29 38.33,42.27 R37.2 ; U26.T3 v2(67.94,27.41)
AM335X_LCD_DATA7: length 51.4
  TOP w0.14: R38.2 v1(39.75,41.91) 39.75,40.23 39.49,39.97 RP2.4
  LY3_SIG1 w0.127: v2(67.94,28.21) 66.66,26.94 66.66,26.13 64.26,23.72 63.25,23.72 61.84,22.31 57.41,22.31 55.23,24.5 48.92,24.5 48.39,25.03 47.54,25.03 43.94,28.63 42.27,28.63 40.78,30.12 40.78,36.4 40.07,37.11 40.07,41.59 v1(39.75,41.91)
  BOTTOM w0.14: U26.T4 v2(67.94,28.21) ; R38.2 v1(39.75,41.91)
AM335X_LCD_DATA8: length 48.1
  TOP w0.14: RP2.3 39.99,39.66 40.77,40.44 v1(40.77,41.91) R39.2
  LY3_SIG1 w0.127: v1(40.77,41.91) 41.16,41.52 41.16,38.25 41.29,38.11 41.29,32.59 41.17,32.46 41.17,30.27 41.52,29.91 42.43,29.01 44.1,29.01 47.59,25.52 50.8,25.52 51.39,24.93 56.21,24.93 56.69,24.45 56.69,24.02 57.15,23.56 60.61,23.56 60.73,23.44 61.1,23.44 61.22,23.56 62.6,23.56 v2(64.65,25.6)
  BOTTOM w0.14: U26.U1 66.93,25.6 v2(64.65,25.6) ; R39.2 v1(40.77,41.91)
AM335X_LCD_DATA9: length 45.7
  TOP w0.14: RP2.2 40.49,39.61 41.16,40.27 41.16,41.29 v1(41.78,41.91) R40.2
  LY3_SIG1 w0.127: v1(41.78,41.91) 41.54,41.67 41.54,38.93 41.68,38.8 41.68,32.43 41.55,32.3 41.55,31.16 41.97,30.74 v1(41.97,30.1)
  LY6_SIG2 w0.127: v2(64.63,26.67) 64.19,27.11 64.18,27.11 63.95,27.34 63.95,27.36 63.37,27.94 55.25,27.94 54.61,28.57 54.1,28.57 53.85,28.32 51.74,28.32 51.04,29.02 48.41,29.02 48.06,29.36 42.7,29.36 v1(41.97,30.1)
  BOTTOM w0.14: v2(64.63,26.67) 65.15,26.67 65.94,27.46 67.1,27.46 U26.U2 ; R40.2 v1(41.78,41.91)
AM335X_LCD_DATA10: length 44.7
  TOP w0.14: RP2.1 41.07,39.63 41.59,40.14 41.59,40.7 v1(42.8,41.91) R41.2
  LY3_SIG1 w0.127: v1(42.8,41.91) 43.05,41.66 43.05,33.26 42,32.21 42,31.35 v1(41.99,31.34)
  LY6_SIG2 w0.127: v2(64.95,28.14) 64.64,28.45 56,28.45 54.49,29.96 51.44,29.96 50.88,29.4 48.83,29.4 48.48,29.75 43.58,29.75 v1(41.99,31.34)
  BOTTOM w0.14: v2(64.95,28.14) 64.9,28.19 64.91,28.21 67.15,28.21 U26.U3 ; R41.2 v1(42.8,41.91)
AM335X_LCD_DATA11: length 43.1
  TOP w0.14: RP3.5 43.57,39.8 43.75,39.98 v1(43.75,41.14) 43.75,41.87 43.81,41.94 R42.2
  LY3_SIG1 w0.127: v1(43.75,41.14) 43.58,40.98 43.58,33.17 v1(42.44,32.03)
  LY6_SIG2 w0.127: v2(64.08,29.46) 63.69,29.07 57.64,29.07 57.02,29.69 55.31,29.69 54.35,30.65 46.8,30.65 46.29,30.13 44.34,30.13 v1(42.44,32.03)
  BOTTOM w0.14: v1(43.75,41.14) 43.81,41.21 R42.2 ; U26.U4 67.15,29.01 66.5,29.01 66.4,28.91 64.69,28.91 64.14,29.46 v2(64.08,29.46)
AM335X_LCD_DATA12: length 43.7
  TOP w0.14: R43.2 v1(44.83,41.91) 44.28,41.36 44.28,39.8 44.06,39.59 RP3.4
  LY3_SIG1 w0.127: v1(44.83,41.91) 44.43,41.51 44.43,41.2 44,40.77 44,30.3 47.77,26.53 50.72,26.53 51.94,25.31 51.94,25.31 53.52,25.31 53.93,25.31 56.87,25.31 56.95,25.39 57.32,25.39 57.59,25.11 57.59,24.96 57.85,24.7 59.45,24.7 59.91,25.16 62.03,25.16 62.08,25.11 63.6,25.11 64.78,26.29 65.37,26.29 v2(66.1,27.01)
  BOTTOM w0.14: R43.2 v1(44.83,41.91) ; v2(66.1,27.01) U26.V2
AM335X_LCD_DATA13: length 43.1
  TOP w0.14: R44.2 v1(45.85,41.91) 44.67,40.73 44.67,39.42 44.57,39.31 RP3.3
  LY3_SIG1 w0.127: v1(45.85,41.91) 44.38,40.44 44.38,30.46 47.93,26.91 50.88,26.91 52.1,25.69 53.36,25.69 53.77,25.69 53.77,25.69 56.71,25.69 56.79,25.77 61.93,25.77 62.39,26.23 62.8,26.23 62.85,26.17 63.47,26.17 v2(64.01,26.71)
  BOTTOM w0.14: R44.2 v1(45.85,41.91) ; U26.V3 65.53,27.81 64.83,27.11 64.29,27.11 64.01,26.82 v2(64.01,26.71)
AM335X_LCD_DATA14: length 43.1
  TOP w0.14: RP3.2 45.06,40.57 45.95,41.46 46.03,41.46 46.15,41.58 46.53,41.58 v1(46.86,41.91) R45.2
  LY3_SIG1 w0.127: v1(46.86,41.91) 45.99,41.03 45.59,41.03 44.76,40.2 44.76,38.06 45.6,37.22 45.6,31.25 48.97,27.88 50.45,27.88 50.78,27.55 50.79,27.55 52.26,26.07 53.21,26.07 53.61,26.07 56.55,26.07 56.63,26.15 61.77,26.15 62.61,26.99 63.5,26.99 63.67,27.15 63.99,27.15 v2(64.34,27.51)
  BOTTOM w0.14: R45.2 v1(46.86,41.91) ; v2(64.34,27.51) 64.34,28.3 64.66,28.61 U26.V4
AM335X_LCD_DATA15: length 44.9
  TOP w0.14: R46.2 47.88,42.06 47,41.18 46.37,41.18 v1(45.57,40.39) 45.57,39.49 45.65,39.42 RP3.1
  LY3_SIG1 w0.127: v1(45.57,40.39) 45.14,39.96 45.14,38.22 45.98,37.38 45.98,31.4 49.13,28.26 50.61,28.26 50.94,27.93 50.94,27.93 52.42,26.45 53.05,26.45 53.45,26.45 53.45,26.45 56.4,26.45 56.47,26.53 61.61,26.53 62.91,27.83 64.11,27.83 64.18,27.9 64.51,27.9 64.66,27.75 66.66,27.75 67.93,29.01 v2(67.94,29.01)
  BOTTOM w0.14: R46.2 47.88,41.78 47.49,41.4 46.57,41.4 46.01,40.84 45.98,40.8 45.95,40.77 45.66,40.47 45.64,40.46 45.57,40.4 v1(45.57,40.39) ; U26.T5 v2(67.94,29.01)
AM335X_LCD_DATA16: length 46
  TOP w0.14: RP1.6 33.79,39.31 v1(32.95,40.16)
  LY3_SIG1 w0.127: v1(32.95,40.16) 32.95,40.77 33.08,40.9 33.08,41.97 33.5,42.38 35.85,42.38 36.23,41.99 36.23,41.58 36.98,40.83 37.35,40.83 38.23,41.71 38.23,41.76 39.21,42.74 47.21,42.74 48.51,41.44 49.29,41.44 50.04,40.68 51.9,40.68 52.43,40.14 58.83,40.14 59.61,40.92 61.25,40.92 61.66,40.51 62.55,40.51 64.23,38.83 64.23,36.02 v2(64.83,35.42)
  BOTTOM w0.14: v2(64.83,35.42) 67.15,35.42 U26.U13
AM335X_LCD_DATA17: length 29.8
  TOP w0.14: RP3.6 43.06,40.3 v1(42.6,40.77)
  LY6_SIG2 w0.127: v2(63.87,35.42) 63.36,35.93 61.4,35.93 61.16,35.69 56.73,35.69 56.41,35.37 56.04,35.37 55.9,35.51 52.94,35.51 52.91,35.47 51.9,35.47 50.07,37.31 46.06,37.31 v1(42.6,40.77)
  BOTTOM w0.14: v2(63.87,35.42) 64.27,35.42 64.67,35.82 66.73,35.82 U26.V13
AM335X_LCD_DATA18: length 50.3
  TOP w0.14: RP1.7 33.29,39.25 32.94,39.6 32.73,39.6 v1(32.14,40.19)
  LY3_SIG1 w0.127: v1(32.14,40.19) 32.14,42.21 32.92,42.99 37.31,42.99 37.82,43.5 48.3,43.5 50.26,41.54 59.02,41.54 59.29,41.82 61.65,41.82 62.23,41.24 63.68,41.24 64.23,40.69 64.23,39.94 64.73,39.45 65.75,39.45 65.84,39.36 66.15,39.36 69.35,39.36 69.93,38.78 69.93,36.05 69.7,35.82 69.14,35.82 v2(68.74,35.41)
  BOTTOM w0.14: U26.R12 v2(68.74,35.41)
AM335X_LCD_DATA19: length 43.6
  TOP w0.14: v1(37.17,41.27) 37.17,40.51 37.99,39.69 RP2.7
  LY3_SIG1 w0.127: v1(37.17,41.27) 37.17,41.99 38.3,43.12 48.14,43.12 50.2,41.06 52.25,41.06 52.79,40.53 58.67,40.53 59.45,41.3 61.62,41.3 62.07,40.86 62.88,40.86 64.51,39.22 65.22,39.22 65.22,39.22 65.66,39.22 65.75,39.13 66.06,39.13 66.06,39.13 67.38,39.13 67.38,39.13 68.78,39.13 69.13,38.78 69.13,36.85 68.89,36.61 68.58,36.61 68.34,36.38 68.34,35.82 v2(67.94,35.41)
  BOTTOM w0.14: U26.T12 v2(67.94,35.41)
AM335X_LCD_DATA20: length 29.7
  TOP w0.14: v1(42.57,39.68) RP3.7
  LY6_SIG2 w0.127: v2(62.35,34.13) 60.84,34.13 60.58,33.87 51.73,33.87 49.22,36.38 45.87,36.38 v1(42.57,39.68)
  BOTTOM w0.14: U26.U12 67.12,34.6 65.49,34.6 65.04,34.14 64.79,34.14 64.7,34.23 64.7,34.23 64.47,34.47 64.37,34.56 62.8,34.56 62.35,34.1 v2(62.35,34.13)
AM335X_LCD_DATA21: length 45.5
  TOP w0.14: RP1.8 32.71,38.84 32.7,38.86 32.7,38.92 32.88,39.1 v1(32.81,39.1)
  LY3_SIG1 w0.127: v1(32.81,39.1) 33.27,39.1 38.36,34.01 38.36,32.09 v1(38.83,31.62)
  LY6_SIG2 w0.127: v1(38.83,31.62) 40,31.62 41.53,33.15 48.83,33.15 49.59,32.39 59.52,32.39 61.62,30.29 63.7,30.29 64.04,30.63 64.04,30.76 64.76,31.48 65.14,31.48 65.37,31.71 65.37,32.35 65.37,32.36 65.37,33.18 66.8,34.61 v2(67.94,34.61)
  BOTTOM w0.14: U26.T11 v2(67.94,34.61)
AM335X_LCD_DATA22: length 46.3
  TOP w0.14: RP2.8 v1(37.41,39.12)
  LY3_SIG1 w0.127: v1(37.41,39.12) 38.23,39.94 38.23,41.17 38.61,41.56 38.61,41.6 39.37,42.35 47.05,42.35 48.35,41.05 48.85,41.05 49.21,40.7 49.21,39.96 48.96,39.71 48.96,37.56 49.26,37.26 49.26,35.57 49.96,34.88 49.96,32.51 51.99,30.47 54.7,30.47 55.45,29.71 55.91,29.71 56.11,29.91 61.34,29.91 61.41,29.97 64.29,29.97 64.46,29.81 64.99,29.81 65.77,30.58 65.77,31.64 v2(67.94,33.81)
  BOTTOM w0.14: U26.T10 v2(67.94,33.81)
AM335X_LCD_DATA23: length 29.7
  TOP w0.14: RP3.8 v1(41.98,39.12)
  LY6_SIG2 w0.127: v2(63.75,32.39) 61.43,32.39 60.32,33.49 50.93,33.49 49.19,35.22 45.88,35.22 v1(41.98,39.12)
  BOTTOM w0.14: v2(63.75,32.39) 64.14,32.77 65.58,32.77 65.85,33.05 67.17,33.05 U26.U10
AM335X_LCD_DISEN: length 29.8
  TOP w0.14: RP4.7 47.26,39.71 v1(46.4,40.58)
  LY6_SIG2 w0.127: v1(46.4,40.58) 48.03,38.95 50.89,38.95 53.24,36.6 58,36.6 58.53,36.07 60.84,36.07 61.66,36.89 61.66,40.14 62.07,40.55 v2(63.81,40.55)
  BOTTOM w0.14: v2(63.81,40.55) 63.83,40.57 66.78,40.57 U26.U18
AM335X_LCD_HSYNC: length 39.6
  TOP w0.14: RP4.6 v1(47.76,40.51)
  LY3_SIG1 w0.127: v2(68.74,29.01) 68.34,29.41 67.51,29.41 66.42,28.32 65.33,28.32 65.11,28.53 64.79,28.53 64.5,28.24 64.2,28.24 64.05,28.09 62.64,28.09 61.46,26.91 56.31,26.91 56.24,26.84 53.3,26.84 52.89,26.83 52.58,26.83 51.1,28.31 51.1,28.31 50.77,28.64 49.28,28.64 46.36,31.56 46.36,37.54 45.52,38.37 45.52,39.51 46.07,40.06 47.31,40.06 v1(47.76,40.51)
  BOTTOM w0.14: U26.R5 v2(68.74,29.01)
AM335X_LCD_PCLK: length 28.5
  TOP w0.14: RP4.8 46.68,38.87 46.41,39.14 v1(46.41,39.15)
  LY3_SIG1 w0.127: v1(46.41,39.15) 47.87,37.69 47.87,36.05 48.63,35.29 48.67,35.29 49.45,34.51 49.45,32.3 51.78,29.96 54.49,29.96 54.75,29.7 54.75,29.69 55.23,29.21 56.12,29.21 56.32,29.4 61.55,29.4 61.62,29.46 v2(63.5,29.46)
  BOTTOM w0.14: U26.V5 66.33,29.41 66.1,29.19 64.77,29.19 64.54,29.43 64.54,29.59 64.26,29.86 63.9,29.86 v2(63.5,29.46)
AM335X_LCD_VSYNC: length 45.7
  TOP w0.14: RP4.5 48.26,38.72 48.16,38.82 48.16,39.85 48.26,39.94 48.26,41.59 v1(48.63,41.95)
  LY6_SIG2 w0.127: v1(48.63,41.95) 47.7,42.87 42.55,42.87 42.23,42.55 42.23,41.41 41.54,40.72 41.54,37.62 45.47,33.69 49.49,33.69 50.11,33.07 59.72,33.07 61.48,31.32 62.9,31.32 v2(63.53,30.68)
  BOTTOM w0.14: U26.U5 67.16,29.79 66.4,29.79 66.12,30.07 65.41,30.07 65.14,29.8 64.66,29.8 64.27,30.19 64.03,30.19 v2(63.53,30.68)
AM335X_MCASP0_ACLKX: length 81.8
  BOTTOM w0.14: U29.4 53.62,26.16 53.94,26.48 56.55,26.48 57.1,25.93 60.47,25.93 61.17,25.23 61.17,24.91 61.23,24.85 61.23,24.3 61.45,24.08 61.45,23.86 61.68,23.63 68.03,23.63 71.63,20.03 77.56,20.03 79.52,21.99 87.61,21.99 89.5,23.88 93.47,23.88 94.05,24.45 98.88,24.45 99.96,25.54 99.96,26.24 99.64,26.56 98.24,26.56 97.84,26.96 97.84,30.31 97.59,30.56 95.15,30.56 94.11,29.52 92.65,29.52 92.39,29.79 92.39,30.69 91.13,31.95 91.13,33.13 90.77,33.49 89.59,34.67 85.76,34.67 85.46,34.37 84.98,34.37 84.63,34.72 84.63,35.12 83.93,35.81 83.76,35.81 83.74,35.83 83.39,35.83 83.37,35.81 83.29,35.81 82.99,35.52 81.71,35.52 81.41,35.81 U26.A13
AM335X_MCASP0_AHCLKR: length 92.9
  TOP w0.14: v2(64.83,30.2) 64.83,29.34 65.61,28.56 65.61,26.94 65.96,26.59 66.33,26.59 67.13,25.79 67.86,25.79 68.23,25.41 68.23,24.89 68.44,24.68 68.44,21.88 66.67,20.11 63.38,20.11 61.49,18.22 60.74,18.22 60.2,17.68 59.83,17.68 59.49,18.01 58.36,18.01 57.71,18.66 57.1,18.66 56.78,18.99 55.41,18.99 54.38,17.97 54.38,13.66 v1(55.14,12.9)
  LY6_SIG2 w0.127: v1(55.14,12.9) 56.34,11.7 56.34,8.62 55.94,8.23 55.18,8.23 53.8,6.85 42.66,6.85 42.18,7.34 34.15,7.34 29.61,11.88 29.61,16.95 26.23,20.33 26.23,20.78 21.98,25.03 16.8,25.03 16.62,24.84 v1(15.7,24.84)
  BOTTOM w0.14: v2(64.83,30.2) 65.04,30.41 66.54,30.41 U26.V6 ; A1.6 15.46,25.09 v1(15.7,24.84)
AM335X_MCASP0_AHCLKX: length 77.6
  TOP w0.14: U12.7 v1(61.91,10.26)
  LY6_SIG2 w0.127: v1(61.91,10.26) 62.17,10 62.17,7.08 65.3,3.95 82.69,3.95 84.94,6.2 87.22,6.2 89,7.98 89,8.71 90.27,9.98 91.19,9.98 92.09,9.98 92.71,10.6 92.71,14.33 91.97,15.07 91.97,20.02 90.99,20.99 90.99,24.23 88.36,26.87 86.76,26.87 83.11,30.51 83.11,30.97 82.62,31.46 82.62,32.04 82.25,32.41 81.91,32.41 80.68,33.64 80.68,36.41 81.68,37.4 82.41,37.4 v2(82.82,36.99)
  BOTTOM w0.14: U26.A14 80.35,36.61 82.43,36.61 v2(82.82,36.99)
AM335X_MCASP0_AXR0: length 85.7
  LY3_SIG1 w0.127: v1(54.27,22.35) 54.27,21.68 56.02,19.94 59.84,19.94 60,19.78 v1(61.34,19.78)
  LY6_SIG2 w0.127: v1(61.34,19.78) 61.34,19.11 61.78,18.67 61.78,13.22 63.53,11.47 63.53,6.79 65.61,4.71 82.09,4.71 84.74,7.37 87.12,7.37 88.24,8.49 88.24,9.95 89.66,11.37 89.66,13.63 88.69,14.6 88.69,16.15 88.01,16.82 88.01,22.58 87.64,22.95 87.64,23.66 87.19,24.12 86.68,24.12 78.75,32.05 78.75,34.41 78.34,34.82 v2(78.34,35.41)
  BOTTOM w0.14: U26.D12 77.94,35.01 v2(78.34,35.41) ; U29.5 v1(54.27,22.35)
AM335X_MCASP0_AXR1: length 62.5
  TOP w0.14: U12.5 61.91,8.96 63.85,7.02 63.94,7.02 v1(64.02,6.93)
  LY6_SIG2 w0.127: v1(64.02,6.93) 64.53,6.93 66.41,5.04 81.95,5.04 87.8,10.9 87.8,12.61 87.63,12.79 87.63,12.81 87.57,12.87 87.57,22.32 87.31,22.57 87.31,23.53 87.05,23.79 86.52,23.79 78.49,31.82 78.18,31.82 77.94,32.05 77.94,35.82 v2(78.34,36.21)
  BOTTOM w0.14: U26.D13 v2(78.34,36.21)
AM335X_MCASP0_FSX: length 84.1
  TOP w0.14: U12.6 58.51,9.61 v1(58.42,9.53)
  LY6_SIG2 w0.127: v1(58.42,9.53) 59.42,8.52 59.42,8.39 64.87,2.94 83.44,2.94 84.89,4.38 87.39,4.38 88.16,5.15 90.94,5.15 94.52,8.73 95.11,8.73 96.91,10.54 96.91,11.19 96.94,11.21 96.94,11.71 97.28,12.05 97.28,14.57 93.7,18.15 93.7,19.72 92.27,21.15 92.27,24.39 88.66,28 87.06,28 84.31,30.75 84.31,31.61 83.38,32.54 82.77,32.54 82.44,32.87 82.29,33.02 82.04,33.02 81.62,33.44 81.62,34.89 82.17,35.43 82.3,35.43 v2(82.96,36.09)
  BOTTOM w0.14: U26.B13 79.89,36.16 80.54,36.16 80.7,36.32 82.87,36.32 82.96,36.23 v2(82.96,36.09)
AM335X_MMC0_CLK: length 60.9
  TOP w0.14: v1(111.02,68.35) 108.13,68.35 106.89,67.11 106.89,64.47 105.39,62.97 104.76,62.97 v1(103.49,61.7) 102.93,62.26 102.93,64.54 103.41,65.02 U1.1
  LY3_SIG1 w0.127: v1(103.49,61.7) 101.81,60.02 97.6,60.02 93.31,55.72 91.56,55.72 90.38,56.9 78.67,56.9 77.29,55.52 74.21,55.52 v1(73.32,54.63)
  BOTTOM w0.14: J4.5 v1(111.02,68.35) ; v1(73.32,54.63) 73.32,53.66 74.76,52.22 74.76,47.73 R132.1
AM335X_MMC0_CMD: length 83.6
  TOP w0.14: R1.1 99.5,67.94 99.2,67.65 v1(98.68,67.65) ; U1.2 v1(104.53,64.34)
  LY6_SIG2 w0.127: v1(98.68,67.65) 97.65,66.62 95.93,66.62 95.71,66.4 95.71,65.92 96.07,65.56 98.41,65.56 98.6,65.37 98.6,65.11 98.41,64.92 95.9,64.92 95.71,64.73 95.71,64.47 95.9,64.29 98.41,64.29 98.6,64.1 98.6,63.84 98.41,63.65 95.9,63.65 95.71,63.46 95.71,62.04 95.9,61.86 98.14,61.86 98.32,61.67 98.32,61.41 98.14,61.22 95.9,61.22 95.71,61.04 95.71,60.76 95.93,60.54 98.29,60.54 99.23,59.6 99.23,57.6 99.25,57.59 99.25,57.22 99.23,57.2 99.23,54.83 98.81,54.41 92.62,54.41 90.57,56.46 79.54,56.46 77.87,54.79 77.87,53.4 76.01,51.54 76.01,50.07 74.84,48.91 74.84,43.41 v2(75.16,43.09)
  BOTTOM w0.14: v2(75.16,43.09) 75.16,43.11 75.52,42.76 75.52,39.83 U26.G18 ; J4.3 v1(98.68,67.65) 99.53,67.65 102.84,64.34 v1(104.53,64.34)
AM335X_MMC0_D0: length 74.7
  TOP w0.14: R2.1 110.78,67.18 v1(111.01,66.95) ; U1.8 v1(104.53,66.99)
  LY6_SIG2 w0.127: v1(104.53,66.99) 105.6,65.92 105.6,54 104.4,52.81 102.17,52.81 101.83,52.48 93,52.48 90.53,54.94 79.76,54.94 78.86,54.04 78.86,52.98 77.86,51.97 77.86,51.18 77,50.32 77,49.58 76.18,48.76 76.18,47.04 80.96,42.25 80.96,41.25 80.48,40.77 79.84,40.77 79.2,40.13 77.45,40.13 v2(75.94,38.61)
  BOTTOM w0.14: J4.7 v1(111.01,66.95) 109.89,66.95 109.14,67.69 106.6,67.69 105.9,66.99 v1(104.53,66.99) ; U26.G16 v2(75.94,38.61)
AM335X_MMC0_D1: length 81.3
  TOP w0.14: U1.7 105.02,67.24 v1(104.45,67.82) 103.41,67.82 102.62,67.03 102.62,65.41 102.04,64.82 R5.1
  LY6_SIG2 w0.127: v1(104.45,67.82) 103.76,67.13 103.76,62.46 104.19,62.03 104.19,60.66 103.7,60.17 103.7,54.1 103.01,53.41 101.96,53.41 101.4,52.86 93.14,52.86 90.51,55.49 79.73,55.49 78.53,54.29 78.53,53.13 77.21,51.81 77.21,51 76.67,50.46 76.67,49.71 75.68,48.73 75.68,46.83 79.64,42.88 79.64,41.25 78.81,40.42 77.06,40.42 75.55,38.91 75.55,38.22 v2(75.14,37.81)
  BOTTOM w0.14: v1(104.45,67.82) 103.94,67.31 103.94,66.62 104.32,66.25 J4.8 ; U26.G15 v2(75.14,37.81)
AM335X_MMC0_D2: length 94.1
  TOP w0.14: U1.6 105.53,67.63 104.86,68.29 102.77,68.29 v1(102.77,68.29) ; R4.1 99.12,65.84 v1(98.71,66.25)
  LY6_SIG2 w0.127: v1(98.71,66.25) 98.75,66.28 100.63,66.28 102.45,64.47 102.45,61.69 102.1,61.34 100.27,61.34 100.08,61.15 100.08,60.89 100.27,60.7 102.1,60.7 102.28,60.52 102.28,60.25 102.1,60.07 100.27,60.07 100.08,59.88 100.08,59.62 100.27,59.43 102.1,59.43 102.28,59.25 102.28,57.84 102.1,57.66 100.3,57.66 100.11,57.47 100.11,57.21 100.3,57.02 102.1,57.02 102.28,56.84 102.28,56.57 102.1,56.39 100.3,56.39 100.11,56.2 100.11,55.94 100.3,55.75 102.1,55.75 102.28,55.57 102.28,54.54 101.36,53.62 92.85,53.62 90.52,55.95 79.58,55.95 78.2,54.57 78.2,53.27 76.34,51.41 76.34,49.94 75.23,48.83 75.23,46.69 76.05,45.87 76.05,43.91 75.92,43.78 v2(75.92,42.68)
  BOTTOM w0.14: J4.1 v1(98.71,66.25) 100.31,64.64 101.17,64.64 102.65,63.17 105.16,63.17 105.49,63.5 105.49,64.26 102.77,66.99 v1(102.77,68.29) ; v2(75.92,42.68) 75.92,42.31 76.34,41.9 U26.F18
